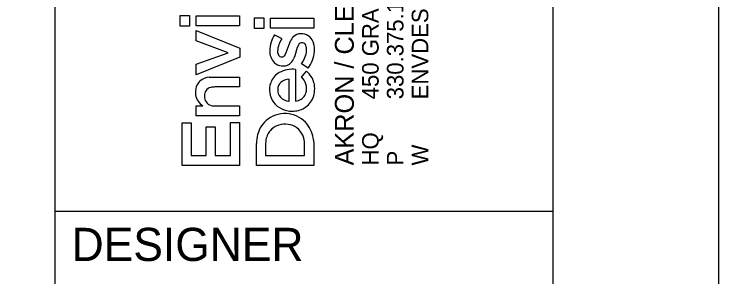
# Model space of a CAD drawing. Extents: x 0 to 34, y 0 to 22.
# Drawn here: x 31.877 to 34, y 2.302 to 3.094 of the extents above; entities that cross this region are included whole.
import ezdxf

# ---------------------------------------------------------------- set-up
doc = ezdxf.new("R2010")
doc.units = 0
for name, color, linetype in [('SH_Border', 7, 'Continuous'), ('SH_Cut_Line', 7, 'Continuous'), ('SH_Data', 7, 'Continuous')]:
    doc.layers.add(name, color=color, linetype=linetype)

msp = doc.modelspace()

# ---------------------------------------------------------------- linework, layer by layer
at = {"layer": 'SH_Border'}
for p, q in [((32, 0.5), (32, 21.5)), ((32, 2.5), (33.5, 2.5))]:
    msp.add_line(p, q, dxfattribs=at)
msp.add_lwpolyline([(1.5, 21.5), (33.5, 21.5), (33.5, 0.5), (1.5, 0.5)], close=True, dxfattribs=at)
at = {"layer": 'SH_Cut_Line'}
msp.add_lwpolyline([(0, 0), (34, 0), (34, 22), (0, 22)], close=True, dxfattribs=at)
at = {"layer": 'SH_Data'}
for p, q in [((32.3771, 3.0582), (32.3771, 3.0903)), ((32.3771, 3.0903), (32.4054, 3.0903)), ((32.4054, 3.0903), (32.4054, 3.0582)), ((32.4254, 3.0594), (32.4254, 3.0893)), ((32.4254, 3.0893), (32.5557, 3.0893)), ((32.5557, 3.0893), (32.5557, 3.0594)), ((32.6005, 3.0511), (32.6005, 3.0832)), ((32.6005, 3.0832), (32.6289, 3.0832)), ((32.6289, 3.0832), (32.6289, 3.0511)), ((32.6489, 3.0523), (32.6489, 3.0822)), ((32.6489, 3.0822), (32.7792, 3.0822)), ((32.7792, 3.0822), (32.7792, 3.0523)), ((32.4054, 3.0582), (32.3771, 3.0582)), ((32.5557, 3.0594), (32.4254, 3.0594)), ((32.4254, 3.0133), (32.4254, 3.0446)), ((32.4254, 3.0446), (32.5567, 2.9913)), ((32.6289, 3.0511), (32.6005, 3.0511)), ((32.7792, 3.0523), (32.6489, 3.0523)), ((32.6615, 3.0321), (32.6827, 3.0203)), ((32.5212, 2.978), (32.4254, 3.0133)), ((32.6967, 2.9787), (32.7048, 3.0026)), ((32.7048, 3.0026), (32.7104, 3.0153)), ((32.7334, 3.001), (32.7298, 2.9933)), ((32.4254, 2.9429), (32.5212, 2.978)), ((32.5567, 2.9913), (32.5567, 2.9644)), ((32.693, 2.9712), (32.6967, 2.9787)), ((32.7298, 2.9933), (32.7221, 2.9688)), ((32.5567, 2.9644), (32.4254, 2.9109)), ((32.7221, 2.9688), (32.7182, 2.9592)), ((32.4254, 2.9109), (32.4254, 2.9429)), ((32.7621, 2.9314), (32.742, 2.9447)), ((32.7245, 2.9275), (32.7246, 2.8319)), ((32.7423, 2.9046), (32.7577, 2.922)), ((32.4644, 2.904), (32.4729, 2.9044)), ((32.4729, 2.9044), (32.5557, 2.9044)), ((32.5557, 2.9044), (32.5557, 2.8746)), ((32.7049, 2.8318), (32.7049, 2.8983)), ((32.5557, 2.8746), (32.4814, 2.8746)), ((32.7036, 2.8317), (32.7049, 2.8318)), ((32.4254, 2.7875), (32.4254, 2.8173)), ((32.4254, 2.8173), (32.4455, 2.8173)), ((32.4822, 2.8173), (32.5557, 2.8173)), ((32.5557, 2.8173), (32.5557, 2.7876)), ((32.5557, 2.7876), (32.4254, 2.7875)), ((32.383, 2.6379), (32.383, 2.766)), ((32.383, 2.766), (32.4101, 2.766)), ((32.4101, 2.766), (32.4101, 2.6683)), ((32.5286, 2.6683), (32.5286, 2.7672)), ((32.5286, 2.7672), (32.5557, 2.7672)), ((32.5557, 2.7672), (32.5557, 2.6379)), ((32.455, 2.6683), (32.455, 2.7549)), ((32.455, 2.7549), (32.4822, 2.7549)), ((32.4822, 2.7549), (32.4822, 2.6683)), ((32.6064, 2.638), (32.6064, 2.704)), ((32.6347, 2.7118), (32.6341, 2.7023)), ((32.6341, 2.7023), (32.6341, 2.6684)), ((32.7515, 2.6683), (32.7515, 2.7024)), ((32.7785, 2.715), (32.7792, 2.7021)), ((32.7792, 2.7021), (32.7792, 2.638)), ((32.4101, 2.6683), (32.455, 2.6683)), ((32.4822, 2.6683), (32.5286, 2.6683)), ((32.6341, 2.6684), (32.7515, 2.6683)), ((32.5557, 2.6379), (32.383, 2.6379)), ((32.7792, 2.638), (32.6064, 2.638))]:
    msp.add_line(p, q, dxfattribs=at)
for points in [[(32.3771, 3.0582), (32.3771, 3.0903), (32.4054, 3.0903), (32.4054, 3.0582)], [(32.4254, 3.0594), (32.4254, 3.0893), (32.5557, 3.0893), (32.5557, 3.0594)], [(32.6005, 3.0511), (32.6005, 3.0832), (32.6289, 3.0832), (32.6289, 3.0511)], [(32.6489, 3.0523), (32.6489, 3.0822), (32.7792, 3.0822), (32.7792, 3.0523)], [(32.4254, 2.9109), (32.4254, 2.9429), (32.5212, 2.978), (32.4254, 3.0133), (32.4254, 3.0446), (32.5567, 2.9913), (32.5567, 2.9644)], [(32.383, 2.6379), (32.383, 2.766), (32.4101, 2.766), (32.4101, 2.6683), (32.455, 2.6683), (32.455, 2.7549), (32.4822, 2.7549), (32.4822, 2.6683), (32.5286, 2.6683), (32.5286, 2.7672), (32.5557, 2.7672), (32.5557, 2.6379)]]:
    msp.add_lwpolyline(points, close=True, dxfattribs=at)
for points in [[(32.6615, 3.0321), (32.6827, 3.0203)], [(32.693, 2.9712), (32.6967, 2.9787), (32.7048, 3.0026), (32.7104, 3.0153)], [(32.7334, 3.001), (32.7298, 2.9933), (32.7221, 2.9688), (32.7182, 2.9592)], [(32.7621, 2.9314), (32.742, 2.9447)], [(32.7245, 2.9275), (32.7246, 2.8319)], [(32.7423, 2.9046), (32.7577, 2.922)], [(32.4644, 2.904), (32.4729, 2.9044), (32.5557, 2.9044), (32.5557, 2.8746), (32.4814, 2.8746)], [(32.7036, 2.8317), (32.7049, 2.8318), (32.7049, 2.8983)], [(32.4254, 2.7875), (32.4254, 2.8173), (32.4455, 2.8173)], [(32.4822, 2.8173), (32.5557, 2.8173), (32.5557, 2.7876), (32.4254, 2.7875)], [(32.7785, 2.715), (32.7792, 2.7021), (32.7792, 2.638), (32.6064, 2.638)], [(32.6064, 2.638), (32.6064, 2.704)], [(32.6347, 2.7118), (32.6341, 2.7023), (32.6341, 2.6684), (32.7515, 2.6683), (32.7515, 2.7024)]]:
    msp.add_lwpolyline(points, dxfattribs=at)
for centre, radius, start, end in [((32.7364, 2.9826), 0.0897, 146.531, 178.7571), ((32.7364, 2.9826), 0.0897, 146.531, 178.7571), ((32.7452, 2.9789), 0.0749, 146.5112, 176.9101), ((32.7452, 2.9789), 0.0749, 146.5112, 176.9101), ((32.7466, 2.9971), 0.0405, 125.5118, 153.4159), ((32.7466, 2.9971), 0.0405, 125.5118, 153.4159), ((32.7406, 3.0026), 0.0326, 80.1719, 122.5197), ((32.7406, 3.0026), 0.0326, 80.1719, 122.5197), ((32.7428, 2.9982), 0.0367, 47.7934, 84.6892), ((32.7428, 2.9982), 0.0367, 47.7934, 84.6892), ((32.7379, 2.9946), 0.0427, 14.9966, 46.2063), ((32.7379, 2.9946), 0.0427, 14.9966, 46.2063), ((32.7438, 2.9963), 0.0114, 76.6609, 155.7053), ((32.7438, 2.9963), 0.0114, 76.6609, 155.7053), ((32.744, 2.9951), 0.0126, 21.5098, 78.5262), ((32.744, 2.9951), 0.0126, 21.5098, 78.5262), ((32.7259, 2.9877), 0.0321, 354.5726, 22.068), ((32.7259, 2.9877), 0.0321, 354.5726, 22.068), ((32.7104, 2.9867), 0.0712, 355.8306, 15.3914), ((32.7104, 2.9867), 0.0712, 355.8306, 15.3914), ((32.6967, 2.9824), 0.0501, 177.5366, 222.7932), ((32.6967, 2.9824), 0.0501, 177.5366, 222.7932), ((32.6931, 2.9823), 0.0228, 178.4747, 211.0868), ((32.6931, 2.9823), 0.0228, 178.4747, 211.0868), ((32.6825, 2.9915), 0.0757, 321.811, 354.7969), ((32.6825, 2.9915), 0.0757, 321.811, 354.7969), ((32.6895, 2.9882), 0.0922, 321.9777, 355.8738), ((32.6895, 2.9882), 0.0922, 321.9777, 355.8738), ((32.6833, 2.9767), 0.0115, 212.2368, 268.3777), ((32.6833, 2.9767), 0.0115, 212.2368, 268.3777), ((32.6834, 2.9759), 0.0107, 267.716, 333.7337), ((32.6834, 2.9759), 0.0107, 267.716, 333.7337), ((32.681, 2.9758), 0.0408, 308.0877, 335.9874), ((32.681, 2.9758), 0.0408, 308.0877, 335.9874), ((32.686, 2.9753), 0.0375, 225.9854, 302.4797), ((32.686, 2.9753), 0.0375, 225.9854, 302.4797), ((32.7024, 2.8691), 0.0558, 118.8308, 160.6244), ((32.7024, 2.8691), 0.0558, 118.8308, 160.6244), ((32.7152, 2.8441), 0.0838, 83.615, 118.2876), ((32.7152, 2.8441), 0.0838, 83.615, 118.2876), ((32.7174, 2.8717), 0.0644, 13.5336, 51.3615), ((32.7174, 2.8717), 0.0644, 13.5336, 51.3615), ((32.4635, 2.8626), 0.0402, 132.2219, 161.6818), ((32.4635, 2.8626), 0.0402, 132.2219, 161.6818), ((32.4687, 2.8543), 0.0499, 94.9696, 130.2225), ((32.4687, 2.8543), 0.0499, 94.9696, 130.2225), ((32.7005, 2.8663), 0.0298, 132.9851, 177.179), ((32.7005, 2.8663), 0.0298, 132.9851, 177.179), ((32.7079, 2.8561), 0.0424, 94.008, 130.8817), ((32.7079, 2.8561), 0.0424, 94.008, 130.8817), ((32.7038, 2.8656), 0.0549, 19.0357, 45.4406), ((32.7038, 2.8656), 0.0549, 19.0357, 45.4406), ((32.4787, 2.8582), 0.056, 162.2736, 187.7919), ((32.4787, 2.8582), 0.056, 162.2736, 187.7919), ((32.4748, 2.8487), 0.025, 103.6865, 182.2187), ((32.4748, 2.8487), 0.025, 103.6865, 182.2187), ((32.4811, 2.8286), 0.046, 89.6049, 105.3284), ((32.4811, 2.8286), 0.046, 89.6049, 105.3284), ((32.7104, 2.8661), 0.0644, 160.5201, 215.7831), ((32.7104, 2.8661), 0.0644, 160.5201, 215.7831), ((32.7017, 2.865), 0.0311, 175.0013, 223.283), ((32.7017, 2.865), 0.0311, 175.0013, 223.283), ((32.7107, 2.8697), 0.047, 344.6059, 17.007), ((32.7107, 2.8697), 0.047, 344.6059, 17.007), ((32.7064, 2.8692), 0.0758, 339.3542, 13.3785), ((32.7064, 2.8692), 0.0758, 339.3542, 13.3785), ((32.4703, 2.858), 0.0476, 188.962, 238.7037), ((32.4703, 2.858), 0.0476, 188.962, 238.7037), ((32.4773, 2.8456), 0.0276, 175.5854, 255.1439), ((32.4773, 2.8456), 0.0276, 175.5854, 255.1439), ((32.7224, 2.8671), 0.035, 288.0077, 343.5508), ((32.7224, 2.8671), 0.035, 288.0077, 343.5508), ((32.7125, 2.8705), 0.0687, 217.7452, 271.6543), ((32.7125, 2.8705), 0.0687, 217.7452, 271.6543), ((32.7089, 2.8736), 0.0423, 225.0619, 262.7974), ((32.7089, 2.8736), 0.0423, 225.0619, 262.7974), ((32.7247, 2.8522), 0.0202, 269.7003, 294.8711), ((32.7247, 2.8522), 0.0202, 269.7003, 294.8711), ((32.7189, 2.8652), 0.0626, 300.9427, 338.7323), ((32.7189, 2.8652), 0.0626, 300.9427, 338.7323), ((32.4818, 2.8595), 0.0422, 254.0916, 270.5284), ((32.4818, 2.8595), 0.0422, 254.0916, 270.5284), ((32.7155, 2.8724), 0.0706, 269.2048, 300.3341), ((32.7155, 2.8724), 0.0706, 269.2048, 300.3341), ((32.6923, 2.7079), 0.0864, 81.194, 125.9984), ((32.6923, 2.7079), 0.0864, 81.194, 125.9984), ((32.6946, 2.7113), 0.0827, 37.8521, 82.402), ((32.6946, 2.7113), 0.0827, 37.8521, 82.402), ((32.6939, 2.7089), 0.0865, 127.2362, 165.148), ((32.6939, 2.7089), 0.0865, 127.2362, 165.148), ((32.6928, 2.6986), 0.0639, 55.6727, 107.2093), ((32.6928, 2.6986), 0.0639, 55.6727, 107.2093), ((32.6859, 2.7057), 0.0931, 5.7333, 37.304), ((32.6859, 2.7057), 0.0931, 5.7333, 37.304), ((32.6889, 2.7078), 0.054, 106.1881, 157.3861), ((32.6889, 2.7078), 0.054, 106.1881, 157.3861), ((32.6929, 2.705), 0.0587, 357.4662, 52.2665), ((32.6929, 2.705), 0.0587, 357.4662, 52.2665), ((32.7143, 2.7028), 0.1078, 164.7861, 179.3704), ((32.7143, 2.7028), 0.1078, 164.7861, 179.3704), ((32.6983, 2.7039), 0.0641, 157.3571, 172.9275), ((32.6983, 2.7039), 0.0641, 157.3571, 172.9275)]:
    msp.add_arc(centre, radius, start, end, dxfattribs=at)

# ---------------------------------------------------------------- texts
for s, height, p in [('450 GRANT ST., AKRON, OH  44311', 0.049846, (32.9749, 2.8374)), ('AKRON / CLEVELAND / COLUMBUS', 0.056969, (32.9001, 2.638)), ('ENVDESIGNGROUP.COM', 0.049846, (33.1244, 2.8374)), ('330.375.1390', 0.049846, (33.0497, 2.8374)), ('HQ ', 0.04985, (32.9749, 2.638)), ('W', 0.0498, (33.1244, 2.638)), ('P', 0.0498, (33.0497, 2.638))]:
    msp.add_text(s, height=height, rotation=90, dxfattribs=at).set_placement(p)
msp.add_text('DESIGNER', height=0.1, dxfattribs=at).set_placement((32.05, 2.35))

doc.saveas('drawing.dxf')
